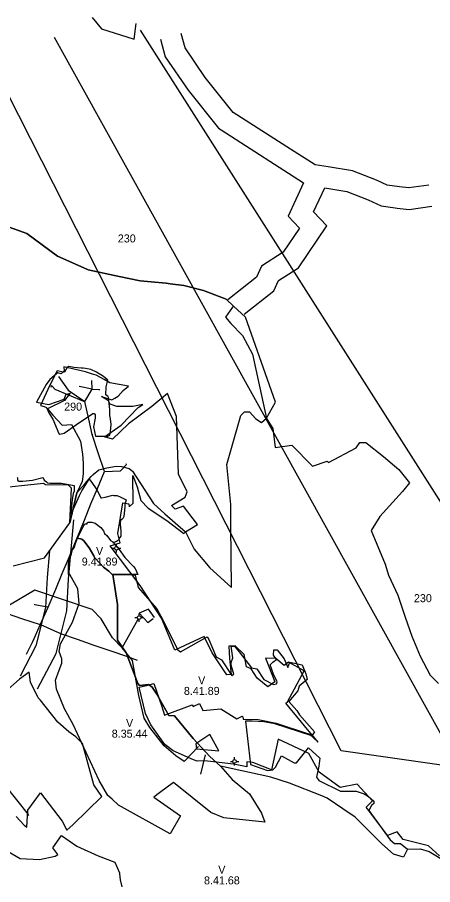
# Model space of a CAD drawing. Extents: x -694504 to -690518, y -983661 to -978958.
# Drawn here: x -692675 to -691897, y -980583 to -978958 of the extents above; entities that cross this region are included whole.
import ezdxf

# ---------------------------------------------------------------- set-up
doc = ezdxf.new("R2010")
doc.units = 0
for name, color, linetype in [('BPEJ', 7, 'Continuous'), ('chráněné ložiskové území', 7, 'Continuous'), ('lokální biocentra', 7, 'Continuous'), ('nadregionální biokoridor', 7, 'Continuous'), ('Natura 2000', 7, 'Continuous'), ('ochranné pásmo radioreleové trasy', 7, 'Continuous'), ('OP vodního zdroje 1 stupně', 7, 'Continuous'), ('regionální biocentrum', 7, 'Continuous'), ('třídy přednosti v ochraně ZP', 7, 'Continuous'), ('vedení NN', 7, 'Continuous'), ('vodní zdroj', 7, 'Continuous'), ('vodovodní řad', 7, 'Continuous')]:
    doc.layers.add(name, color=color, linetype=linetype)

msp = doc.modelspace()

# ---------------------------------------------------------------- linework, layer by layer
at = {"layer": 'BPEJ'}
for points in [[(-692581.4, -979613.8), (-692586.4, -979622.8), (-692588.4, -979622.8), (-692600.4, -979619.8), (-692614.4, -979646.8), (-692631.4, -979684.8), (-692624.4, -979686.8), (-692620.4, -979688.8), (-692615.4, -979699.8), (-692608.4, -979710.8), (-692597.4, -979737.8), (-692595.4, -979738.8), (-692587.4, -979736.8), (-692564.4, -979720.8), (-692533.4, -979699.8), (-692531.4, -979699.8), (-692530.4, -979700.8), (-692529.4, -979702.8), (-692529.4, -979708.8), (-692532.4, -979724.8), (-692528.4, -979742.8), (-692510.4, -979742.8), (-692505.4, -979742.8), (-692501.4, -979740.8), (-692500.4, -979733.8), (-692499.4, -979720.8), (-692500.4, -979709.8), (-692501.4, -979703.8), (-692501.4, -979692.8), (-692504.4, -979669.8), (-692505.4, -979667.8), (-692508.4, -979665.8), (-692509.4, -979664.8), (-692508.4, -979649.8), (-692505.4, -979637.8), (-692513.4, -979630.8), (-692526.4, -979622.8), (-692537.4, -979617.8), (-692547.4, -979615.8), (-692551.4, -979614.8), (-692555.4, -979614.8), (-692569.4, -979613.8), (-692578.4, -979611.8), (-692581.4, -979613.8)], [(-692495.4, -979941.8), (-692492.4, -979945.8), (-692484.4, -979954.8), (-692473.4, -979969.8), (-692457.4, -979986.8), (-692454.4, -979990.8), (-692449.4, -980001.8), (-692454.4, -980001.8), (-692461.4, -980001.8), (-692496.4, -980001.8), (-692497.4, -980001.8), (-692500.4, -979998.8), (-692503.4, -979995.8), (-692513.4, -979987.8), (-692520.4, -979980.8), (-692530.4, -979969.8), (-692531.4, -979966.8), (-692540.4, -979951.8), (-692550.4, -979938.8), (-692554.4, -979935.8), (-692562.4, -979933.8), (-692551.4, -979911.8), (-692549.4, -979907.8), (-692548.4, -979906.8), (-692544.4, -979906.8), (-692544.4, -979904.8), (-692542.4, -979903.8), (-692539.4, -979903.8), (-692535.4, -979903.8), (-692529.4, -979905.8), (-692518.4, -979913.8), (-692513.4, -979919.8), (-692511.4, -979924.8), (-692507.4, -979928.8), (-692500.4, -979937.8), (-692496.4, -979940.8), (-692496.4, -979941.8), (-692495.4, -979941.8)], [(-692496.4, -980001.8), (-692487.4, -980057.8), (-692487.4, -980124.8), (-692471.4, -980148.8), (-692461.4, -980174.8), (-692449.4, -980205.8), (-692446.4, -980209.8), (-692429.4, -980207.8), (-692422.4, -980212.8), (-692413.4, -980225.8), (-692391.4, -980265.8), (-692380.4, -980266.8), (-692345.4, -980308.8), (-692314.4, -980342.8), (-692294.4, -980360.8), (-692272.4, -980385.8), (-692240.4, -980412.8), (-692217.4, -980448.8), (-692211.4, -980465.8), (-692288.4, -980457.8), (-692312.4, -980447.8), (-692382.4, -980391.8), (-692408.4, -980410.8), (-692419.4, -980418.8), (-692369.4, -980453.8), (-692388.4, -980487.8), (-692485.4, -980433.8), (-692497.4, -980422.8), (-692505.4, -980415.8), (-692521.4, -980387.8), (-692570.4, -980282.8), (-692586.4, -980253.8), (-692601.4, -980216.8), (-692603.4, -980199.8), (-692596.4, -980180.8), (-692591.4, -980167.8), (-692591.4, -980159.8), (-692596.4, -980145.8), (-692594.4, -980131.8), (-692571.4, -980090.8), (-692559.4, -980055.8), (-692561.4, -980028.8), (-692576.4, -980001.8), (-692579.4, -980001.8), (-692579.4, -979981.8), (-692578.4, -979976.8), (-692573.4, -979962.8), (-692571.4, -979955.8), (-692568.4, -979951.8), (-692565.4, -979941.8), (-692562.4, -979933.8), (-692554.4, -979935.8), (-692550.4, -979938.8), (-692540.4, -979951.8), (-692531.4, -979966.8), (-692530.4, -979969.8), (-692520.4, -979980.8), (-692513.4, -979987.8), (-692503.4, -979995.8), (-692500.4, -979998.8), (-692497.4, -980001.8), (-692496.4, -980001.8)], [(-691944.4, -980516.8), (-691951.4, -980531.8), (-691970.4, -980525.8), (-691992.4, -980506.8), (-692042.4, -980456.8), (-692065.4, -980440.8), (-692094.4, -980420.8), (-692104.4, -980416.8), (-692165.4, -980392.8), (-692200.4, -980381.8), (-692294.4, -980360.8), (-692314.4, -980342.8), (-692345.4, -980308.8), (-692380.4, -980266.8), (-692391.4, -980265.8), (-692413.4, -980225.8), (-692422.4, -980212.8), (-692429.4, -980207.8), (-692446.4, -980209.8), (-692449.4, -980205.8), (-692461.4, -980174.8), (-692471.4, -980148.8), (-692487.4, -980124.8), (-692487.4, -980057.8), (-692496.4, -980001.8), (-692461.4, -980001.8), (-692454.4, -980002.8), (-692448.4, -980025.8), (-692413.4, -980065.8), (-692406.4, -980079.8), (-692374.4, -980142.8), (-692369.4, -980146.8), (-692319.4, -980118.8), (-692316.4, -980123.8), (-692302.4, -980155.8), (-692292.4, -980161.8), (-692273.4, -980190.8), (-692269.4, -980188.8), (-692274.4, -980171.8), (-692274.4, -980166.8), (-692271.4, -980157.8), (-692274.4, -980135.8), (-692268.4, -980135.8), (-692259.4, -980146.8), (-692236.4, -980176.8), (-692226.4, -980178.8), (-692213.4, -980198.8), (-692195.4, -980207.8), (-692189.4, -980206.8), (-692188.4, -980202.8), (-692195.4, -980188.8), (-692201.4, -980170.8), (-692196.4, -980165.8), (-692189.4, -980160.8), (-692195.4, -980152.8), (-692194.4, -980142.8), (-692188.4, -980142.8), (-692175.4, -980159.8), (-692168.4, -980175.8), (-692164.4, -980165.8), (-692141.4, -980170.8), (-692134.4, -980187.8), (-692132.4, -980198.8), (-692147.4, -980210.8), (-692149.4, -980219.8), (-692166.4, -980239.8), (-692151.4, -980256.8), (-692146.4, -980264.8), (-692118.4, -980296.8), (-692123.4, -980303.8), (-692192.4, -980281.8), (-692213.4, -980277.8), (-692235.4, -980276.8), (-692247.4, -980276.8), (-692238.4, -980357.8), (-692206.4, -980368.8), (-692196.4, -980367.8), (-692191.4, -980362.8), (-692180.4, -980341.8), (-692156.4, -980354.8), (-692152.4, -980354.8), (-692129.4, -980326.8), (-692108.4, -980345.8), (-692110.4, -980360.8), (-692114.4, -980381.8), (-692110.4, -980387.8), (-692069.4, -980407.8), (-692040.4, -980407.8), (-692025.4, -980412.8), (-692017.4, -980417.8), (-692007.4, -980426.8), (-692007.4, -980430.8), (-692011.4, -980434.8), (-692016.4, -980443.8), (-691976.4, -980498.8), (-691968.4, -980505.8), (-691957.4, -980505.8), (-691944.4, -980516.8)]]:
    msp.add_lwpolyline(points, close=True, dxfattribs=at)
for points in [[(-692675.4, -979819.8), (-692674.4, -979820.8), (-692674.4, -979824.8), (-692672.4, -979826.8), (-692664.4, -979826.8), (-692646.4, -979824.8), (-692627.4, -979819.8), (-692626.4, -979820.8), (-692624.4, -979824.8), (-692620.4, -979827.8), (-692618.4, -979829.8), (-692613.4, -979830.8), (-692599.4, -979830.8), (-692592.4, -979830.8), (-692568.4, -979834.8), (-692568.4, -979845.8), (-692570.4, -979849.8), (-692572.4, -979861.8), (-692574.4, -979880.8), (-692574.4, -979888.8), (-692558.4, -979853.8), (-692554.4, -979844.8), (-692540.4, -979822.8), (-692537.4, -979826.8), (-692525.4, -979843.8), (-692518.4, -979857.8), (-692517.4, -979857.8), (-692510.4, -979856.8), (-692496.4, -979852.8), (-692494.4, -979853.8), (-692488.4, -979853.8), (-692483.4, -979855.8), (-692471.4, -979861.8), (-692473.4, -979870.8), (-692473.4, -979874.8), (-692475.4, -979892.8), (-692477.4, -979896.8), (-692478.4, -979897.8), (-692481.4, -979899.8), (-692482.4, -979901.8), (-692482.4, -979907.8), (-692481.4, -979919.8), (-692481.4, -979929.8), (-692483.4, -979932.8), (-692486.4, -979937.8), (-692489.4, -979939.8), (-692494.4, -979941.8), (-692495.4, -979941.8)], [(-692692.4, -980520.8), (-692669.4, -980533.8), (-692633.4, -980535.8), (-692604.4, -980529.8), (-692599.4, -980526.8), (-692608.4, -980513.8), (-692592.4, -980490.8), (-692563.4, -980510.8), (-692523.4, -980528.8), (-692492.4, -980540.8), (-692483.4, -980560.8), (-692483.4, -980562.8), (-692482.4, -980573.8), (-692479.4, -980586.8)], [(-691944.4, -980516.8), (-691920.4, -980515.8), (-691903.4, -980520.8), (-691878.4, -980535.8), (-691872.4, -980535.8), (-691855.4, -980527.8)]]:
    msp.add_lwpolyline(points, dxfattribs=at)
at = {"layer": 'chráněné ložiskové území'}
msp.add_lwpolyline([(-691332.6, -980056.6), (-691597, -980399.4), (-692068.6, -980332.4), (-692715.6, -979056.8)], dxfattribs=at)
at = {"layer": 'lokální biocentra'}
for points in [[(-692534.8, -978957.6), (-692517.6, -978978.8), (-692456.1, -978998.2), (-692452.6, -978968.8)], [(-692677.1, -980455.5), (-692662.1, -980471.8), (-692656.9, -980475.3), (-692655.6, -980443.3), (-692631.7, -980410.9), (-692590.7, -980464), (-692582.2, -980481.2), (-692570.5, -980470), (-692516.4, -980417.9), (-692531.5, -980395.7), (-692552.9, -980318.6), (-692565.6, -980305.7), (-692578.6, -980296.6), (-692599.2, -980278.8), (-692632.4, -980236.6), (-692636.1, -980232.9), (-692650.6, -980203.5), (-692652.9, -980185), (-692671, -980198.1), (-692698, -980221.7)]]:
    msp.add_lwpolyline(points, dxfattribs=at)
at = {"layer": 'nadregionální biokoridor'}
for points in [[(-691904.2, -979272.1), (-691941.5, -979277.2), (-691959.4, -979275.3), (-691982.2, -979272), (-692002, -979262.9), (-692047.3, -979245.1), (-692092.9, -979237.7), (-692117.3, -979233.8), (-692163.1, -979204.5), (-692270.4, -979135.7), (-692323.1, -979070), (-692360.9, -979014.4), (-692368.1, -978987.9)], [(-692406.7, -978998.3), (-692397.8, -979031.3), (-692355.3, -979093.8), (-692298.1, -979165), (-692293.1, -979168.6), (-692184.7, -979238.1), (-692138.8, -979267.5), (-692167.7, -979330.3), (-692146.4, -979352.4), (-692177.1, -979397.7), (-692217.6, -979423.6), (-692227, -979444.6), (-692280.9, -979486.9)], [(-692250.4, -979514), (-692194.6, -979469.9), (-692186, -979450.9), (-692148.6, -979426.9), (-692095.2, -979348.1), (-692120, -979322.3), (-692099.3, -979277.2), (-692058, -979283.9), (-692017.7, -979299.8), (-691993.7, -979310.7), (-691967, -979314.7), (-691963.6, -979315.1), (-691940.9, -979317.5), (-691898.8, -979311.7)], [(-692637.4, -980216.3), (-692602.3, -980150), (-692582.3, -980069.8), (-692579.2, -980010.2), (-692569.4, -979899.1)], [(-692614.7, -979957.2), (-692619.1, -980007.4), (-692622, -980063.9), (-692640, -980135.6), (-692669.8, -980192.1)]]:
    msp.add_lwpolyline(points, dxfattribs=at)
at = {"layer": 'Natura 2000'}
for points in [[(-692697.2, -979348.4), (-692657, -979362.5), (-692599.8, -979405), (-692545, -979429.7), (-692542.1, -979431), (-692484.2, -979443.1), (-692444.8, -979451.3), (-692424.6, -979453.2), (-692396.2, -979456), (-692388.6, -979456.8), (-692363.3, -979460.4), (-692326, -979469.5), (-692283.6, -979485.6), (-692270.1, -979498.7), (-692271.8, -979500.9), (-692285.1, -979519.3), (-692275, -979531.4), (-692253.2, -979554), (-692234.7, -979588.8), (-692208.3, -979709.6), (-692196.4, -979728), (-692192.2, -979763.5), (-692160.9, -979759.3), (-692122.1, -979798.7), (-692094.4, -979789.3), (-692092.2, -979791.6), (-692040.4, -979764.3), (-692033.4, -979754.1), (-692022.1, -979754.1), (-691988.9, -979780.7), (-691960.5, -979805.2), (-691940.3, -979830), (-691953.5, -979846), (-691996.3, -979893.2), (-692012.2, -979919.1), (-691986.1, -979982.2), (-691980, -980003.1), (-691962, -980040.6), (-691948.8, -980081.7), (-691936.2, -980117.2), (-691920.7, -980154.7), (-691901.8, -980190.6), (-691886.4, -980206.2)], [(-691884.1, -980529.3), (-691904.8, -980510.2), (-691952.3, -980498.2), (-691963.7, -980484), (-691981.7, -980491), (-692016.7, -980443.9), (-692021.4, -980437.5), (-692009.8, -980425.9), (-692038.6, -980394.7), (-692070.2, -980401), (-692109.8, -980372.2), (-692129.2, -980337.1), (-692186.5, -980310.4), (-692198.9, -980367.8), (-692234.1, -980353.8), (-692245.4, -980352.6), (-692245.1, -980356.6), (-692244.9, -980362), (-692263.6, -980358.5), (-692269.2, -980357.4), (-692275.4, -980356.7), (-692301.8, -980353.6), (-692324.3, -980350.9), (-692338, -980351.3), (-692344.8, -980349), (-692383.2, -980332.5), (-692398.7, -980320.3), (-692425.2, -980283.7), (-692434.8, -980262.4), (-692447, -980212.6), (-692432.8, -980209.5), (-692419.2, -980205.8), (-692404.4, -980249.2), (-692399.5, -980265.4), (-692347.4, -980245.8), (-692345.6, -980249), (-692333.9, -980243.8), (-692327.7, -980256.9), (-692294, -980253.2), (-692263.9, -980272.1), (-692253.7, -980267.2), (-692252.3, -980268.6), (-692252.1, -980272.7), (-692223.8, -980273.5), (-692190.2, -980280.3), (-692127.7, -980300.7), (-692111.7, -980315.9), (-692117.3, -980309.2), (-692128.5, -980295.8), (-692151.4, -980267.9), (-692166.3, -980249.7), (-692171.9, -980242.8), (-692169, -980240.4), (-692137.6, -980182.1), (-692166.9, -980165.9), (-692175.5, -980172.1), (-692190.9, -980159.1), (-692210.2, -980158.6), (-692203.9, -980174.4), (-692192.9, -980202.6), (-692205.8, -980212.3), (-692226, -980196.1), (-692236.7, -980178.5), (-692245.6, -980174.6), (-692250.2, -980151.6), (-692266.8, -980135.6), (-692278.8, -980136.2), (-692277.4, -980158.9), (-692274.2, -980188.9), (-692282.7, -980189.8), (-692309.9, -980148.3), (-692324.8, -980118), (-692380.1, -980143.8), (-692405.1, -980083.7), (-692445.2, -980022.3), (-692500.8, -979948.1), (-692482.4, -979942.3), (-692486.7, -979925.2), (-692477.5, -979867.3), (-692466.2, -979869.6), (-692465.8, -979875), (-692457.8, -979868), (-692458.6, -979816.1), (-692450.6, -979837.6), (-692443.6, -979862.9), (-692430.1, -979877.6), (-692394.7, -979900.5), (-692362.8, -979925.1), (-692360.1, -979922), (-692337.8, -979908), (-692364, -979873.5), (-692379.6, -979879.3), (-692385.9, -979872.6), (-692360.9, -979856.6), (-692357, -979846.8), (-692373.1, -979814), (-692376.9, -979705.4), (-692393.4, -979662.3), (-692422.8, -979687.2), (-692466.6, -979719.4), (-692496.8, -979748), (-692511.5, -979743.5), (-692480.2, -979721.9), (-692448.6, -979688.9), (-692439.7, -979683), (-692458.4, -979686.9), (-692488.9, -979686.8), (-692500.9, -979682.7), (-692504.5, -979676), (-692517.5, -979668.3), (-692497.8, -979674.1), (-692492.4, -979671.5), (-692485.8, -979667.8), (-692476.7, -979656.8), (-692466.7, -979649), (-692501.5, -979642.4), (-692512.5, -979636.1), (-692527.5, -979628.2), (-692532, -979626.8), (-692547.4, -979622), (-692587.9, -979612.7), (-692587.2, -979620), (-692592.8, -979625.6), (-692599.4, -979624), (-692601.8, -979625.4), (-692613.8, -979636.3), (-692621.1, -979645.6), (-692639.2, -979678.9), (-692615.7, -979683.3), (-692587, -979673), (-692583.7, -979663.8), (-692576.1, -979662.1), (-692586.7, -979675.7), (-692618.2, -979691), (-692608.5, -979702.9), (-692591.1, -979722), (-692573.2, -979720.6), (-692556.7, -979751.6), (-692552.8, -979776.5), (-692551.8, -979793.2), (-692551.9, -979813.3), (-692553.6, -979827.6), (-692563.7, -979848.4), (-692576.5, -979905), (-692573.2, -979840.1), (-692578.9, -979834.2), (-692622.5, -979833.6), (-692626, -979831.5), (-692720.8, -979841.1)]]:
    msp.add_lwpolyline(points, dxfattribs=at)
at = {"layer": 'ochranné pásmo radioreleové trasy'}
for p, q in [((-692444.8, -978981.7), (-690710.2, -981710)), ((-692605.8, -978994.5), (-690996.6, -981898.9))]:
    msp.add_line(p, q, dxfattribs=at)
at = {"layer": 'OP vodního zdroje 1 stupně'}
for points in [[(-692418.3, -980082.4), (-692429, -980066.7), (-692447, -980074.3), (-692430.5, -980091.6), (-692420.8, -980084.1)], [(-692314.6, -980301.8), (-692340.8, -980319), (-692339.1, -980328.2), (-692297.6, -980332), (-692314.6, -980301.8)]]:
    msp.add_lwpolyline(points, dxfattribs=at)
at = {"layer": 'regionální biocentrum'}
msp.add_lwpolyline([(-692682.8, -979985.7), (-692623.8, -979970.6), (-692576.5, -979905), (-692563.7, -979848.4), (-692548, -979831.1), (-692536.5, -979817.9), (-692532.7, -979814.5), (-692522.4, -979805.3), (-692507.2, -979801.7), (-692490.1, -979798.5), (-692479.6, -979799.3), (-692465.6, -979803.3), (-692459.4, -979808.2), (-692420.1, -979868.4), (-692398.9, -979888.1), (-692360.1, -979922), (-692343.6, -979954.1), (-692314.5, -979989.5), (-692274, -980026), (-692274.9, -979909.9), (-692275, -979870.4), (-692282.6, -979795.9), (-692256.4, -979703.9), (-692249.4, -979696.9), (-692240.4, -979696.9), (-692228.4, -979709.9), (-692217.4, -979716.9), (-692208.4, -979708.9), (-692191.3, -979678.9), (-692247.6, -979519.3), (-692270.1, -979498.7), (-692283.6, -979485.6), (-692326, -979469.5), (-692363.3, -979460.4), (-692388.6, -979456.8), (-692396.2, -979456), (-692424.6, -979453.2), (-692444.8, -979451.3), (-692484.2, -979443.1), (-692542.1, -979431), (-692545, -979429.7), (-692599.8, -979405), (-692657, -979362.5), (-692697.2, -979348.4)], dxfattribs=at)
at = {"layer": 'vedení NN'}
for points in [[(-692598.1, -979630.6), (-692580, -979656), (-692548.3, -979677.4)], [(-692535.1, -979654.1), (-692535.7, -979637.9)], [(-692549.6, -979677.4), (-692550.5, -979677.4), (-692604, -979655.1), (-692610.6, -979648.1), (-692612.2, -979649.6), (-692611.5, -979650.4)], [(-692535.1, -979654.1), (-692559, -979649.6)], [(-692548.3, -979677.4), (-692535.1, -979654.1)], [(-692535.1, -979654.1), (-692522.1, -979654.8), (-692520.4, -979654.9)], [(-692548.3, -979677.4), (-692549.6, -979677.4)], [(-692534.7, -979739.5), (-692540.8, -979710.9), (-692548.3, -979677.4)], [(-692534.7, -979739.5), (-692533.5, -979739.1)], [(-692511.7, -979809), (-692523.4, -979773.6), (-692534.7, -979739.5)], [(-692511.7, -979809), (-692481.7, -979807.2), (-692470.5, -979795.6), (-692471.3, -979794.2)], [(-692617, -980063.2), (-692602.9, -980029.3), (-692590.7, -979999.7), (-692577.5, -979967.9), (-692564.4, -979936.1), (-692548.9, -979900), (-692537.1, -979869.6), (-692524.9, -979840.8), (-692511.7, -979809)], [(-692618.3, -980063), (-692642.3, -980058.5), (-692642, -980057.2)], [(-692706.4, -980070.6), (-692666.9, -980084.4), (-692632.2, -980095.3)], [(-692631.7, -980095), (-692617, -980063.2)], [(-692618.3, -980063), (-692617, -980063.2)], [(-692631.3, -980094.3), (-692631.7, -980094.1), (-692632.2, -980095.3)], [(-692631.3, -980094.3), (-692631.2, -980094.4), (-692631.5, -980095.1), (-692631.7, -980095)], [(-692631.3, -980094.3), (-692630.8, -980094.5), (-692631.3, -980095.7), (-692594.3, -980112.4), (-692562.8, -980123.2), (-692531.4, -980134), (-692500, -980144.8), (-692468.5, -980155.7), (-692450.8, -980162.4)], [(-692632.2, -980095.3), (-692646.6, -980127.8), (-692658.5, -980151.5)], [(-692872.7, -980177.9), (-692850.9, -980205), (-692829.1, -980232.4), (-692807.3, -980259.8), (-692785.5, -980287.1), (-692763.7, -980314.5), (-692741.9, -980341.9), (-692720, -980369.2), (-692698.2, -980396.6), (-692676.4, -980424), (-692654.6, -980451.3)], [(-692653.7, -980452.3), (-692654.6, -980453.1)]]:
    msp.add_lwpolyline(points, dxfattribs=at)
at = {"layer": 'vodní zdroj'}
for p, q in [((-692489.1, -979949.2), (-692489.1, -979944.8)), ((-692497, -979952.6), (-692492.6, -979952.6)), ((-692489.1, -979960.5), (-692489.1, -979956.1)), ((-692485.7, -979952.6), (-692481.3, -979952.6)), ((-692446.8, -980079.1), (-692446.8, -980074.7)), ((-692454.6, -980082.5), (-692450.2, -980082.5)), ((-692446.8, -980090.4), (-692446.8, -980086)), ((-692443.4, -980082.5), (-692439, -980082.5)), ((-692275.8, -980352), (-692271.4, -980352)), ((-692268, -980348.6), (-692268, -980344.2)), ((-692264.5, -980352), (-692260.1, -980352)), ((-692268, -980359.8), (-692268, -980355.4))]:
    msp.add_line(p, q, dxfattribs=at)
for centre in [(-692489.1, -979952.6), (-692446.8, -980082.5), (-692268, -980352)]:
    msp.add_circle(centre, 3.43, dxfattribs=at)
at = {"layer": 'vodovodní řad'}
msp.add_line((-692478.6, -980139.1), (-692448.9, -980085.3), dxfattribs=at)
for points in [[(-692335.7, -980324.3), (-692362.6, -980352.1), (-692377.8, -980341.4), (-692400.1, -980322.6), (-692426.9, -980288.7), (-692437.7, -980270.8), (-692447.3, -980228.4), (-692459, -980163.2), (-692478.6, -980139.1), (-692496.5, -980120.3), (-692517.9, -980084.6), (-692534.9, -980067.6), (-692642, -980031.4), (-692700, -980065.3), (-692763.3, -980082.1), (-692985.5, -980110.3)], [(-692323.1, -980339.4), (-692331.7, -980376.2)]]:
    msp.add_lwpolyline(points, dxfattribs=at)

# ---------------------------------------------------------------- texts
at = {"layer": 'třídy přednosti v ochraně ZP'}
for s, p in [('230', (-692486.7, -979379.4)), ('290', (-692587.2, -979694.6)), ('V', (-692527.6, -979965)), ('9.41.89', (-692554.3, -979985)), ('230', (-691932.1, -980053.6)), ('V', (-692336.3, -980207.4)), ('8.41.89', (-692363, -980227.4)), ('V', (-692471.4, -980287.5)), ('8.35.44', (-692498.1, -980307.5)), ('V', (-692298.6, -980562.5)), ('8.41.68', (-692325.3, -980582.5))]:
    msp.add_text(s, height=15, dxfattribs=at).set_placement(p)

doc.saveas('drawing.dxf')
